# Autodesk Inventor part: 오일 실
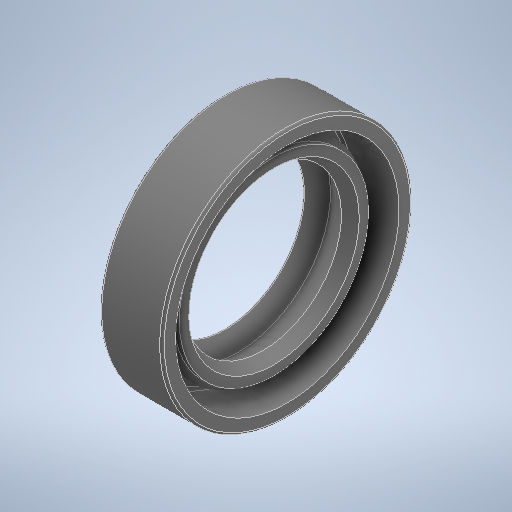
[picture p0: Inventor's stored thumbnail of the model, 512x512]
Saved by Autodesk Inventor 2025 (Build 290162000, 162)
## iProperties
Created: 2024-08
Part Number: 오일 실
Material: 고무
Description: 오일-실
Document SubType Name: Modeling
Designer: deana
Density: 0.93 g/cm^3
Appearance: 기본값
Author: jhkim
Sending System: Autodesk Inventor 2025
Preprocessor: ST-DEVELOPER v20
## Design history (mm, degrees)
feature "Solid1"
node "솔리드1"
